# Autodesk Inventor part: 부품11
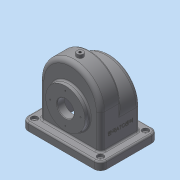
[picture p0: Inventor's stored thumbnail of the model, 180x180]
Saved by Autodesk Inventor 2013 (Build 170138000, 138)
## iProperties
Created: 2017-11
Part Number: 부품11
Material: 일반
Document SubType Name: Modeling
Designer: Administrator
Density: 1 g/cm^3
Author: Administrator
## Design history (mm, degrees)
sketch "스케치1"
  geometry: L1 (58, 40)-(58, -40); L2 (58, -40)-(-58, -40); L3 (-58, -40)-(-58, 40); A1 r 58 centre (0, 40) between (0, 98) and (-58, 40); A2 r 58 centre (0, 40) between (58, 40) and (0, 98); 5 further points
  constraints: 6 end point, 4 point on circle, 2 centre point, 2 point on line, 2 tangent, 1 concentric, 1 horizontal, 1 horizontal alignment, 1 midpoint, 1 parallel, 1 vertical, 1 vertical alignment, 8 other
  dimensions: "d5" = 58 radius of A1; "d71" = 116 distance between parallel lines of L3 L1; "d73" = 80 distance from line of L2 A1.centre
extrude "돌출1" new body sketch "스케치1" stored distance "d7" = 38; taper "d8" = 0 deg
sketch "스케치3"
  geometry: L1 (-58, 17)-(-58, -40); L2 (-58, -40)-(58, -40); L3 (58, 17)-(58, -40); A1 r 58 centre (0, 17) between (58, 17) and (-58, 17); 2 further points
  constraints: 6 end point, 2 point on circle, 1 centre point, 1 horizontal alignment, 1 parallel, 1 perpendicular, 1 point on line, 1 tangent, 1 vertical, 1 vertical alignment
  dimensions: "d10" = 116 diameter of A1; "d11" = 57 distance from line of A1.centre L2
extrude "돌출2" join sketch "스케치3" distance "d12" = 38; taper "d13" = 0 deg
feature "쉘4" dims "d25" = 5
fillet "모깎기1" dims "d31" = 8
fillet "모깎기2" dims "d32" = 3
sketch "스케치8"
  geometry: L1 (-50, -40)-(50, -40) reference; C1 r 37.5 at (0, 25); 1 further point
  constraints: 1 centre point, 1 vertical alignment
  dimensions: "d39" = 75 diameter of C1; "d93" = 65 distance from line of C1.centre L1
extrude "돌출6" join sketch "스케치8" distance "d41" = 9; taper "d42" = 0 deg
sketch "스케치9"
  geometry: L1 (-50, -40)-(50, -40) reference; C1 r 31 at (0, 25); 1 further point
  constraints: 1 centre point, 1 vertical alignment
  dimensions: "d43" = 62 diameter of C1; "d94" = 65 distance from line of L1 C1.centre
extrude "돌출7" join sketch "스케치9" distance "d45" = 10; taper "d46" = 0 deg
sketch "스케치10"
  geometry: L1 (-50, -65)-(50, -65) reference; C1 r 16 at (0, 0); 1 further point
  constraints: 1 centre point, 1 vertical alignment
  dimensions: "d47" = 32 diameter of C1; "d95" = 65 distance from line of C1.centre L1
extrude "돌출8" cut sketch "스케치10" stored distance "d49" = 10; taper "d50" = 0 deg
sketch "스케치11"
  geometry: L1 (-50, -65)-(50, -65) reference; A1 r 29 centre (0, 0) between (0, 29) and (29, 0); 3 further points
  constraints: 4 point on circle, 3 vertical alignment, 2 horizontal alignment, 1 centre point
  dimensions: "d51" = 58 diameter of A1; "d96" = 65 distance from line of L1 A1.centre
hole "구멍1" sketch "스케치11" at (0, 29), (29, 0), (-29, 0), (0, -29) diameter "d53" = 2.459; stored, may be unused: countersink angle "d57" = 90 deg, drill point angle "d59" = 118 deg; dims "d54" = 6, "d55" = 4, "d56" = 2, "d58" = 8
sketch "스케치12"
  geometry: L1 (-50, -65)-(50, -65) reference; A1 r 26 centre (0, 0) between (0, 26) and (0, -26); 3 further points
  constraints: 4 point on circle, 3 vertical alignment, 2 horizontal alignment, 1 centre point
  dimensions: "d60" = 52 diameter of A1; "d97" = 65 distance from line of L1 A1.centre
hole "구멍2" sketch "스케치12" at (0, 26), (0, -26), (26, 0), (-26, 0) diameter "d63" = 2.459; stored, may be unused: countersink angle "d67" = 90 deg, drill point angle "d69" = 118 deg; dims "d64" = 6, "d65" = 4, "d66" = 2, "d68" = 8
sketch "스케치14"
  geometry: 1 further point
sketch "스케치15"
  geometry: L1 (-25, 17)-(125, 17); L2 (125, 17)-(125, -93); L3 (125, -93)-(-25, -93); L4 (-25, -93)-(-25, 17); L5 (108, -8)-(108, -68) reference; 4 further points
  constraints: 8 end point, 3 midpoint, 2 parallel, 1 horizontal, 1 horizontal alignment, 1 perpendicular, 1 vertical alignment
  dimensions: "d88" = 150 distance of L1.start L1.end; "d90" = 110 distance of L1.end L2.end
extrude "돌출10" join sketch "스케치15" distance "d91" = 15; taper "d92" = 0 deg
sketch "스케치16"
  geometry: L1 (22, -22)-(128, -22); L2 (128, -22)-(128, -88); L3 (128, -88)-(22, -88); L4 (22, -88)-(22, -22); L5 (150, 0)-(150, -110) reference; 4 further points
  constraints: 8 end point, 3 midpoint, 2 parallel, 1 horizontal, 1 horizontal alignment, 1 perpendicular, 1 vertical alignment
  dimensions: "d98" = 106 distance of L1.start L1.end; "d100" = 66 distance of L1.end L2.end
extrude "돌출11" cut sketch "스케치16" distance "d101" = 15; taper "d102" = 0 deg
node "작업 평면2"
sketch "스케치17"
  geometry: C1 r 6 at (-75, -36); 1 further point
  constraints: 1 centre point, 1 coincident
  dimensions: "d104" = 12 diameter of C1
extrude "돌출12" join sketch "스케치17" stored distance "d105" = 15; taper "d106" = 0 deg
hole "구멍4" diameter "d109" = 4.459; stored, may be unused: countersink angle "d113" = 90 deg, drill point angle "d115" = 118 deg; dims "d107" = 10, "d108" = 10, "d110" = 20, "d111" = 4, "d112" = 2, "d114" = 25
sketch "스케치18"
  geometry: 1 further point
fillet "모깎기6" dims "d116" = 12
fillet "모깎기7" dims "d117" = 3
sketch "스케치19"
  geometry: 1 further point
fillet "모깎기8" dims "d118" = 3
chamfer "모따기1" distance "d119" = 1; stored, may be unused: second distance "d120" = 2, angle "d121" = 45 deg
fillet "모깎기9" dims "d122" = 3
hole "구멍5" diameter "d125" = 5; stored, may be unused: countersink angle "d129" = 90 deg, drill point angle "d131" = 0 deg; dims "d123" = 10, "d124" = 10, "d126" = 20, "d127" = 12, "d128" = 5, "d130" = 15
hole "구멍6" diameter "d134" = 5; stored, may be unused: countersink angle "d138" = 90 deg, drill point angle "d140" = 0 deg; dims "d132" = 10, "d133" = 10, "d135" = 20, "d136" = 12, "d137" = 5, "d139" = 15
hole "구멍7" diameter "d143" = 5; stored, may be unused: countersink angle "d147" = 90 deg, drill point angle "d149" = 0 deg; dims "d141" = 10, "d142" = 10, "d144" = 20, "d145" = 12, "d146" = 5, "d148" = 15
hole "구멍8" diameter "d152" = 5; stored, may be unused: countersink angle "d156" = 90 deg, drill point angle "d158" = 0 deg; dims "d150" = 10, "d151" = 10, "d153" = 20, "d154" = 12, "d155" = 5, "d157" = 15
sketch "스케치20"
  geometry: L1 (-21.887, -13.398)-(27.887, -13.398); L2 (27.887, -13.398)-(27.887, -20.602); L3 (27.887, -20.602)-(-21.887, -20.602); L4 (-21.887, -20.602)-(-21.887, -13.398); L5 (-40, -57)-(46, -57) reference; L6 (-35, 23)-(-35, -39) reference; 4 further points
  constraints: 2 midpoint, 1 horizontal alignment, 1 vertical alignment, 2 other
  dimensions: "d159" = 40 distance from line of L5 point (3, -17); "d160" = 38 distance from line of L6 point (3, -17); "d161" = 49.77477 distance of L1.start L1.end; "d162" = 7.20489 distance of L1.end L2.end; "d163" = 24.88738 distance of point (3, -17) point (27.887, -17)
feature "엠보싱1" sketch "스케치20" dims "d5" = 58, "d71" = 116, "d73" = 80, "d164" = 0.5, "d165" = 0
node "솔리드1"
other parameters: "d103" = -144
